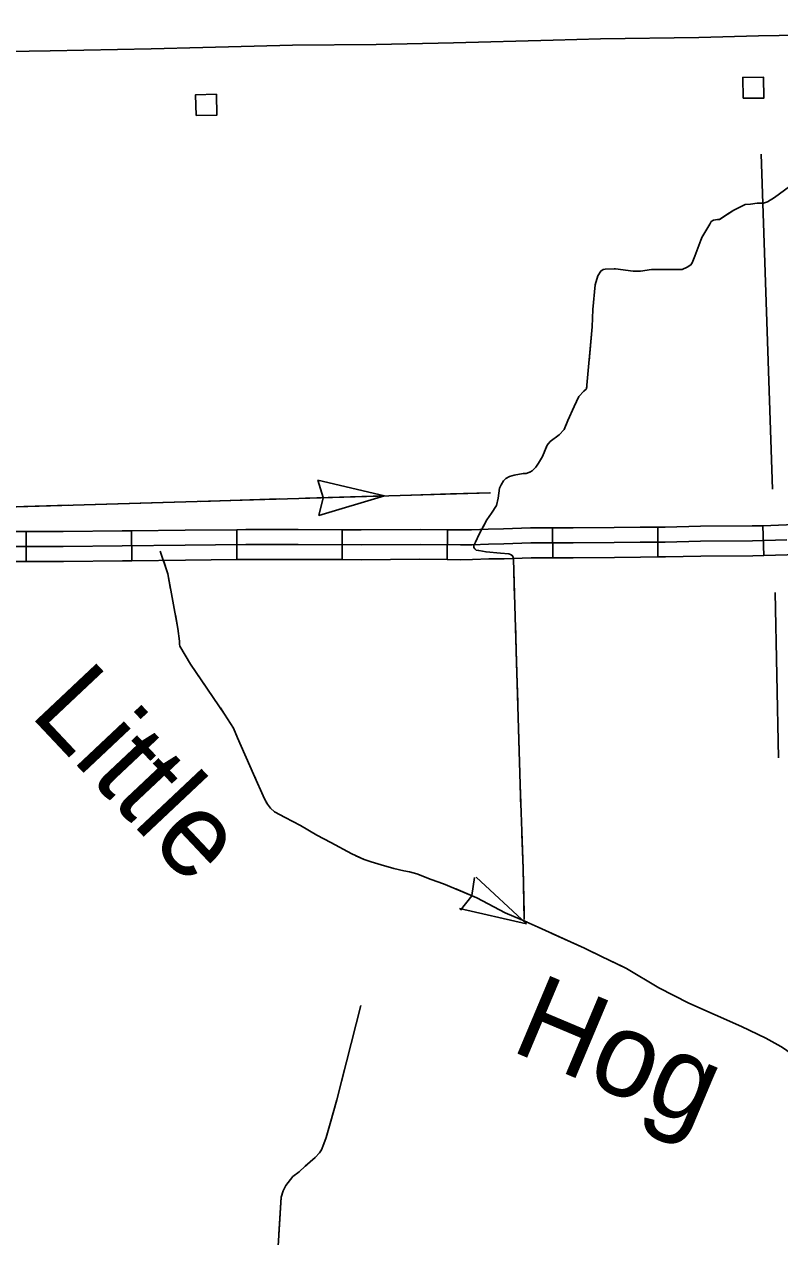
# Model space of a CAD drawing. Extents: x 1084508 to 1142749, y 1057638 to 1093403.
# Drawn here: x 1118442 to 1119631, y 1063081 to 1064990 of the extents above; entities that cross this region are included whole.
import ezdxf

# ---------------------------------------------------------------- set-up
doc = ezdxf.new("R2010")
doc.units = 0
for name, color, linetype in [('Level 10', 7, 'Continuous'), ('Level 32', 7, 'Continuous'), ('Level 35', 7, 'Continuous'), ('Level 43', 7, 'Continuous'), ('Level 5', 7, 'Continuous'), ('Level 56', 7, 'Continuous')]:
    doc.layers.add(name, color=color, linetype=linetype)

msp = doc.modelspace()

# ---------------------------------------------------------------- linework, layer by layer
at = {"layer": 'Level 10'}
for points in [[(1119597.6, 1064972), (1119728.3, 1064974.1), (1119827.1, 1064974.3), (1119932.5, 1064976.3), (1119997.7, 1064977.1), (1120106.4, 1064976.8), (1120263.7, 1064977.1), (1120357.1, 1064976.8), (1120427.6, 1064978.5), (1120539.7, 1064980), (1120644.2, 1064981.1), (1120772.1, 1064983.1), (1120856.2, 1064984.7), (1120960.9, 1064988.1), (1121106.6, 1064989.8), (1121176.1, 1064990.1)], [(1117926.9, 1064944.3), (1118033.7, 1064941.7), (1118119.5, 1064940.9), (1118180.1, 1064942.2), (1118251.8, 1064944.1), (1118382.3, 1064946.7), (1118482.6, 1064948.3), (1118641.4, 1064951.2), (1118722.9, 1064953.3), (1118864.3, 1064957.1), (1118996, 1064958.1), (1119117.7, 1064960.9), (1119274.3, 1064965.3), (1119348.8, 1064967), (1119503.6, 1064969.4), (1119597.6, 1064972)]]:
    msp.add_lwpolyline(points, dxfattribs=at)
at = {"layer": 'Level 32'}
for p, q in [((1119273.7, 1064150.2), (1119273.6, 1064197.2)), ((1119439.4, 1064151.5), (1119439.3, 1064198.6)), ((1119605.8, 1064153.7), (1119604.3, 1064200.8)), ((1118445, 1064144.4), (1118445.1, 1064191.4)), ((1118611, 1064145.7), (1118610.5, 1064192.7)), ((1118776.7, 1064147.4), (1118776.3, 1064194.5)), ((1118942.1, 1064147.4), (1118942.3, 1064194.4)), ((1119107.6, 1064147.3), (1119108.3, 1064194.4))]:
    msp.add_line(p, q, dxfattribs=at)
for points in [[(1119108.3, 1064194.4), (1119128.5, 1064194.1), (1119146.1, 1064194.4), (1119172, 1064195.4), (1119196.3, 1064195.8), (1119238.7, 1064197.2), (1119273.6, 1064197.2)], [(1119273.6, 1064197.2), (1119305.8, 1064197.3), (1119370.2, 1064197.8), (1119411.3, 1064198.5), (1119439.3, 1064198.6)], [(1119439.3, 1064198.6), (1119450.6, 1064198.6), (1119506.1, 1064200), (1119587.8, 1064200.3), (1119604.3, 1064200.8)], [(1119604.3, 1064200.8), (1119641.9, 1064201.9), (1119711.5, 1064202.9), (1119770.3, 1064204)], [(1118278.7, 1064188.9), (1118319.4, 1064190.1), (1118403, 1064191.5), (1118445.1, 1064191.4)], [(1118403.2, 1064167.9), (1118503.3, 1064167.9), (1118596.2, 1064169), (1118695.4, 1064170.1), (1118790.5, 1064171.1), (1118873.1, 1064171.2), (1118972.1, 1064170.8), (1119064.8, 1064171.4), (1119128.6, 1064170.6), (1119146.7, 1064170.8), (1119172.7, 1064171.9), (1119196.9, 1064172.2), (1119239.1, 1064173.6), (1119305.9, 1064173.8), (1119370.5, 1064174.3), (1119411.5, 1064175), (1119450.9, 1064175.1), (1119506.5, 1064176.4), (1119588.2, 1064176.7), (1119642.4, 1064178.4)], [(1118445.1, 1064191.4), (1118503.2, 1064191.4), (1118596, 1064192.6), (1118610.5, 1064192.7)], [(1118610.5, 1064192.7), (1118695.2, 1064193.6), (1118776.3, 1064194.5)], [(1118776.3, 1064194.5), (1118790.4, 1064194.6), (1118873.1, 1064194.7), (1118942.3, 1064194.4)], [(1118942.3, 1064194.4), (1118972.1, 1064194.3), (1119064.9, 1064195), (1119108.3, 1064194.4)], [(1118280, 1064141.9), (1118320.4, 1064143), (1118403.4, 1064144.4), (1118445, 1064144.4)], [(1118445, 1064144.4), (1118503.5, 1064144.3), (1118596.5, 1064145.5), (1118611, 1064145.7)], [(1118611, 1064145.7), (1118695.7, 1064146.6), (1118776.7, 1064147.4)], [(1118776.7, 1064147.4), (1118790.7, 1064147.5), (1118873, 1064147.6), (1118942.1, 1064147.4)], [(1118942.1, 1064147.4), (1118972.1, 1064147.2), (1119064.7, 1064147.9), (1119107.6, 1064147.3)], [(1119107.6, 1064147.3), (1119128.6, 1064147), (1119147.4, 1064147.3), (1119173.3, 1064148.4), (1119197.4, 1064148.7), (1119239.6, 1064150.1), (1119273.7, 1064150.2)], [(1119273.7, 1064150.2), (1119306, 1064150.3), (1119370.8, 1064150.7), (1119411.7, 1064151.4), (1119439.4, 1064151.5)], [(1119439.4, 1064151.5), (1119451.2, 1064151.5), (1119506.8, 1064152.9), (1119588.6, 1064153.2), (1119605.8, 1064153.7)], [(1119605.8, 1064153.7), (1119642.9, 1064154.8), (1119712.3, 1064155.8), (1119771.2, 1064156.9)]]:
    msp.add_lwpolyline(points, dxfattribs=at)
at = {"layer": 'Level 43'}
for p, q in [((1119009, 1064247.7), (1118904.2, 1064272.5)), ((1118904.2, 1064272.5), (1118912.4, 1064245)), ((1119009, 1064247.7), (1118905.8, 1064216.7)), ((1118905.8, 1064216.7), (1118912.4, 1064244.6)), ((1119150.4, 1063647.1), (1119146.6, 1063618.7)), ((1119232.3, 1063574.1), (1119153.3, 1063647.3)), ((1119128.8, 1063595.7), (1119146.4, 1063618.3)), ((1119232.3, 1063574.1), (1119127.2, 1063598))]:
    msp.add_line(p, q, dxfattribs=at)
for points in [[(1118258.4, 1064904.9), (1118130.6, 1064904.9), (1118110, 1064898.7), (1118110, 1064880.1), (1118114.1, 1064859.5), (1118134.7, 1064830.6), (1118126.5, 1064810), (1118079.1, 1064766.7), (1118023.4, 1064731.6), (1118000.7, 1064711), (1117998.7, 1064673.9), (1118011.2, 1064258.9), (1118023.4, 1064224.5), (1118039.4, 1064214.6), (1118233.8, 1064224.9), (1119175.8, 1064252.6)], [(1119654.3, 1064740.4), (1119622.6, 1064717.2), (1119611.9, 1064710.8), (1119605.5, 1064708.2), (1119595.6, 1064708.2), (1119584.9, 1064706.9), (1119576.8, 1064706.1), (1119558.8, 1064697.5), (1119536, 1064682.9), (1119533, 1064682.5), (1119527, 1064681.6), (1119523.2, 1064679.5), (1119521, 1064675.2), (1119508.6, 1064654.2), (1119497.5, 1064625), (1119493.2, 1064614.3), (1119491, 1064611.3), (1119485.5, 1064607.9), (1119477.3, 1064604), (1119454.2, 1064604), (1119429.3, 1064604), (1119411.8, 1064601.5), (1119400.2, 1064601.5), (1119372.3, 1064605.3), (1119356.1, 1064604.5), (1119353.1, 1064604), (1119349.2, 1064601.5), (1119344.5, 1064594.2), (1119340.6, 1064580), (1119336.8, 1064541), (1119335.9, 1064513.6), (1119326.9, 1064416.3), (1119322.6, 1064412.4), (1119314.9, 1064404.3), (1119307.6, 1064388.4), (1119297.3, 1064366.1), (1119291.8, 1064352.4), (1119283.6, 1064343.8), (1119269.9, 1064333.1), (1119264.8, 1064327.5), (1119257.5, 1064309.9), (1119251.5, 1064299.2), (1119247.2, 1064292.8), (1119244.6, 1064290.2), (1119241.2, 1064287.2), (1119237.8, 1064285.1), (1119231.8, 1064282.9), (1119227.1, 1064282.9), (1119212.9, 1064280.4), (1119205.6, 1064278.2), (1119200.1, 1064274.8), (1119196.2, 1064271.4), (1119192.8, 1064264.9), (1119190.2, 1064259.8), (1119187.6, 1064243.9), (1119185.1, 1064232.8), (1119177.4, 1064220.3), (1119170.1, 1064210), (1119158.1, 1064187.3), (1119152.1, 1064174.9), (1119149.5, 1064169.8), (1119149.5, 1064166.3), (1119151.2, 1064164.2), (1119153.4, 1064162.5), (1119157.2, 1064161.6), (1119168.8, 1064159.5), (1119191.5, 1064157.7), (1119204.4, 1064156.5), (1119207.4, 1064155.6), (1119209.9, 1064153.9), (1119211.6, 1064151.3), (1119212.1, 1064147.9), (1119214.2, 1064075.4), (1119222.4, 1063793.3), (1119227.1, 1063660.9), (1119229, 1063581.1)], [(1119607.8, 1064709.1), (1119605.5, 1064708.2), (1119595.6, 1064708.2), (1119584.9, 1064706.9), (1119576.8, 1064706.1), (1119558.8, 1064697.5), (1119549.6, 1064691.6)], [(1119549.6, 1064691.6), (1119536, 1064682.9), (1119533, 1064682.5), (1119527, 1064681.6), (1119523.2, 1064679.5), (1119521, 1064675.2), (1119508.6, 1064654.2), (1119507.4, 1064651.1)], [(1119492, 1064612.7), (1119491, 1064611.3), (1119485.5, 1064607.9), (1119477.3, 1064604), (1119454.2, 1064604), (1119429.3, 1064604), (1119411.8, 1064601.5), (1119400.2, 1064601.5), (1119372.3, 1064605.3), (1119370.7, 1064605.2)], [(1119341.8, 1064584.1), (1119340.6, 1064580), (1119336.8, 1064541), (1119335.9, 1064513.6), (1119331, 1064460.4)], [(1119327.2, 1064419.2), (1119326.9, 1064416.3), (1119322.6, 1064412.4), (1119314.9, 1064404.3), (1119307.6, 1064388.4), (1119297.3, 1064366.1), (1119291.8, 1064352.4), (1119283.6, 1064343.8), (1119269.9, 1064333.1), (1119264.8, 1064327.5), (1119260.7, 1064317.6)], [(1119236.9, 1064284.8), (1119231.8, 1064282.9), (1119227.1, 1064282.9), (1119212.9, 1064280.4), (1119205.6, 1064278.2), (1119200.1, 1064274.8), (1119196.2, 1064271.4), (1119192.8, 1064264.9), (1119190.2, 1064259.8), (1119187.6, 1064243.9), (1119185.1, 1064232.8), (1119177.4, 1064220.3), (1119170.1, 1064210), (1119164.2, 1064198.8)], [(1118553.5, 1064234.3), (1118677.7, 1064237.9)], [(1118719.1, 1064239.1), (1118843.4, 1064242.8)], [(1118884.8, 1064244), (1119009, 1064247.7)], [(1119050.4, 1064248.9), (1119112.6, 1064250.7)], [(1119112.6, 1064250.7), (1119174.7, 1064252.5)], [(1118387.8, 1064229.4), (1118512.1, 1064233)], [(1118656, 1064160.9), (1118667.7, 1064125.2), (1118683.5, 1064039.1), (1118686, 1064019), (1118686, 1064014.3), (1118686.9, 1064010.9), (1118703.4, 1063983), (1118757.3, 1063904.3), (1118771.2, 1063882), (1118777.7, 1063866.8), (1118802.8, 1063809.5), (1118820.1, 1063770.7), (1118824.5, 1063762.4), (1118829.7, 1063756.2), (1118835.9, 1063750.6), (1118852.7, 1063741.6)], [(1118660.8, 1064146.2), (1118667.7, 1064125.2), (1118672.2, 1064101)], [(1119212, 1064149.2), (1119213.8, 1064087.8)], [(1118679.7, 1064060.3), (1118683.5, 1064039.1), (1118686, 1064019), (1118686, 1064014.3), (1118686.9, 1064010.9), (1118703.4, 1063983), (1118727.1, 1063948.4)], [(1119215.1, 1064046.4), (1119216.8, 1063984.3)], [(1119216.8, 1063984.3), (1119218.6, 1063922.2)], [(1118750.5, 1063914.2), (1118757.3, 1063904.3), (1118771.2, 1063882), (1118777.7, 1063866.8), (1118802.8, 1063809.5), (1118805.6, 1063803.2)], [(1119219.8, 1063880.8), (1119222.4, 1063793.3), (1119223.7, 1063756.5)], [(1118822.8, 1063765.6), (1118824.5, 1063762.4), (1118829.7, 1063756.2), (1118835.9, 1063750.6), (1118852.7, 1063741.6), (1118876.5, 1063728.9), (1118902.2, 1063713.7), (1118924.5, 1063702.3), (1118927.4, 1063700.7)], [(1118852.7, 1063741.6), (1118876.5, 1063728.9), (1118902.2, 1063713.7), (1118924.5, 1063702.3), (1118957.7, 1063684.3), (1118976.9, 1063675.3), (1118987.7, 1063671.6), (1119003.8, 1063666.9), (1119023.7, 1063661.3), (1119039.1, 1063657.6), (1119048.1, 1063655.8), (1119059.6, 1063652.7), (1119082.2, 1063643.7), (1119102, 1063637.2), (1119154.4, 1063615.2), (1119199, 1063591.6), (1119222.5, 1063581.4), (1119251, 1063568.7), (1119323.8, 1063535.8), (1119350.5, 1063522.8), (1119390.1, 1063503.9), (1119440.9, 1063473.2), (1119488, 1063449.1), (1119570.7, 1063412.2), (1119609.1, 1063394.2), (1119632.6, 1063380.9)], [(1119225.1, 1063715.1), (1119227.1, 1063660.9), (1119228.8, 1063590.9)], [(1118964, 1063681.3), (1118976.9, 1063675.3), (1118987.7, 1063671.6), (1119003.8, 1063666.9), (1119023.7, 1063661.3), (1119039.1, 1063657.6), (1119048.1, 1063655.8), (1119059.6, 1063652.7), (1119082.2, 1063643.7)], [(1119121, 1063629.2), (1119154.4, 1063615.2), (1119199, 1063591.6), (1119222.5, 1063581.4), (1119233.4, 1063576.5)], [(1119271.2, 1063559.6), (1119323.8, 1063535.8), (1119327.8, 1063533.9)], [(1119327.8, 1063533.9), (1119350.5, 1063522.8), (1119383.8, 1063506.9)], [(1119419.6, 1063486.1), (1119440.9, 1063473.2), (1119488, 1063449.1), (1119530.5, 1063430.1)], [(1118971.8, 1063445.3), (1118933.8, 1063296.8), (1118923.3, 1063259.8), (1118916.9, 1063237.8), (1118913.6, 1063227.8), (1118909.7, 1063218.4), (1118906.4, 1063213.4), (1118900, 1063206.2), (1118884.2, 1063192.5), (1118874.4, 1063183.9), (1118864.4, 1063176.3), (1118853.6, 1063162), (1118849.3, 1063153.7), (1118846.1, 1063144), (1118839.6, 1063032.5)], [(1119568.3, 1063413.3), (1119570.7, 1063412.2), (1119609.1, 1063394.2), (1119632.6, 1063380.9), (1119641.9, 1063375), (1119652.5, 1063366.3), (1119662.7, 1063360.4), (1119677.7, 1063355.5)], [(1118946.1, 1063344.9), (1118933.8, 1063296.8), (1118923.3, 1063259.8), (1118916.9, 1063237.8), (1118913.6, 1063227.8), (1118912.6, 1063225.3)], [(1118886.1, 1063194.2), (1118884.2, 1063192.5), (1118874.4, 1063183.9), (1118864.4, 1063176.3), (1118853.6, 1063162), (1118849.3, 1063153.7), (1118846.1, 1063144), (1118842.7, 1063085.5)]]:
    msp.add_lwpolyline(points, dxfattribs=at)
at = {"layer": 'Level 5'}
for points in [[(1119601.7, 1064785.6), (1119619.5, 1064258.1)], [(1119623.8, 1064095.5), (1119629, 1063835.5)]]:
    msp.add_lwpolyline(points, dxfattribs=at)
at = {"layer": 'Level 56'}
for points in [[(1119573.3, 1064873.6), (1119572.9, 1064906.3), (1119605.7, 1064906.7), (1119606.1, 1064874)], [(1118712.3, 1064846.5), (1118711.6, 1064879.1), (1118744.4, 1064879.8), (1118745, 1064847.1)]]:
    msp.add_lwpolyline(points, close=True, dxfattribs=at)

# ---------------------------------------------------------------- texts
at = {"layer": 'Level 35'}
msp.add_text('Little', height=132.58, rotation=313.2783, dxfattribs=at).set_placement((1118448.8, 1063903.4))
at = {"layer": 'Level 43'}
msp.add_text('Hog', height=132.58, rotation=337.1716, dxfattribs=at).set_placement((1119204.8, 1063375.4))

doc.saveas('drawing.dxf')
